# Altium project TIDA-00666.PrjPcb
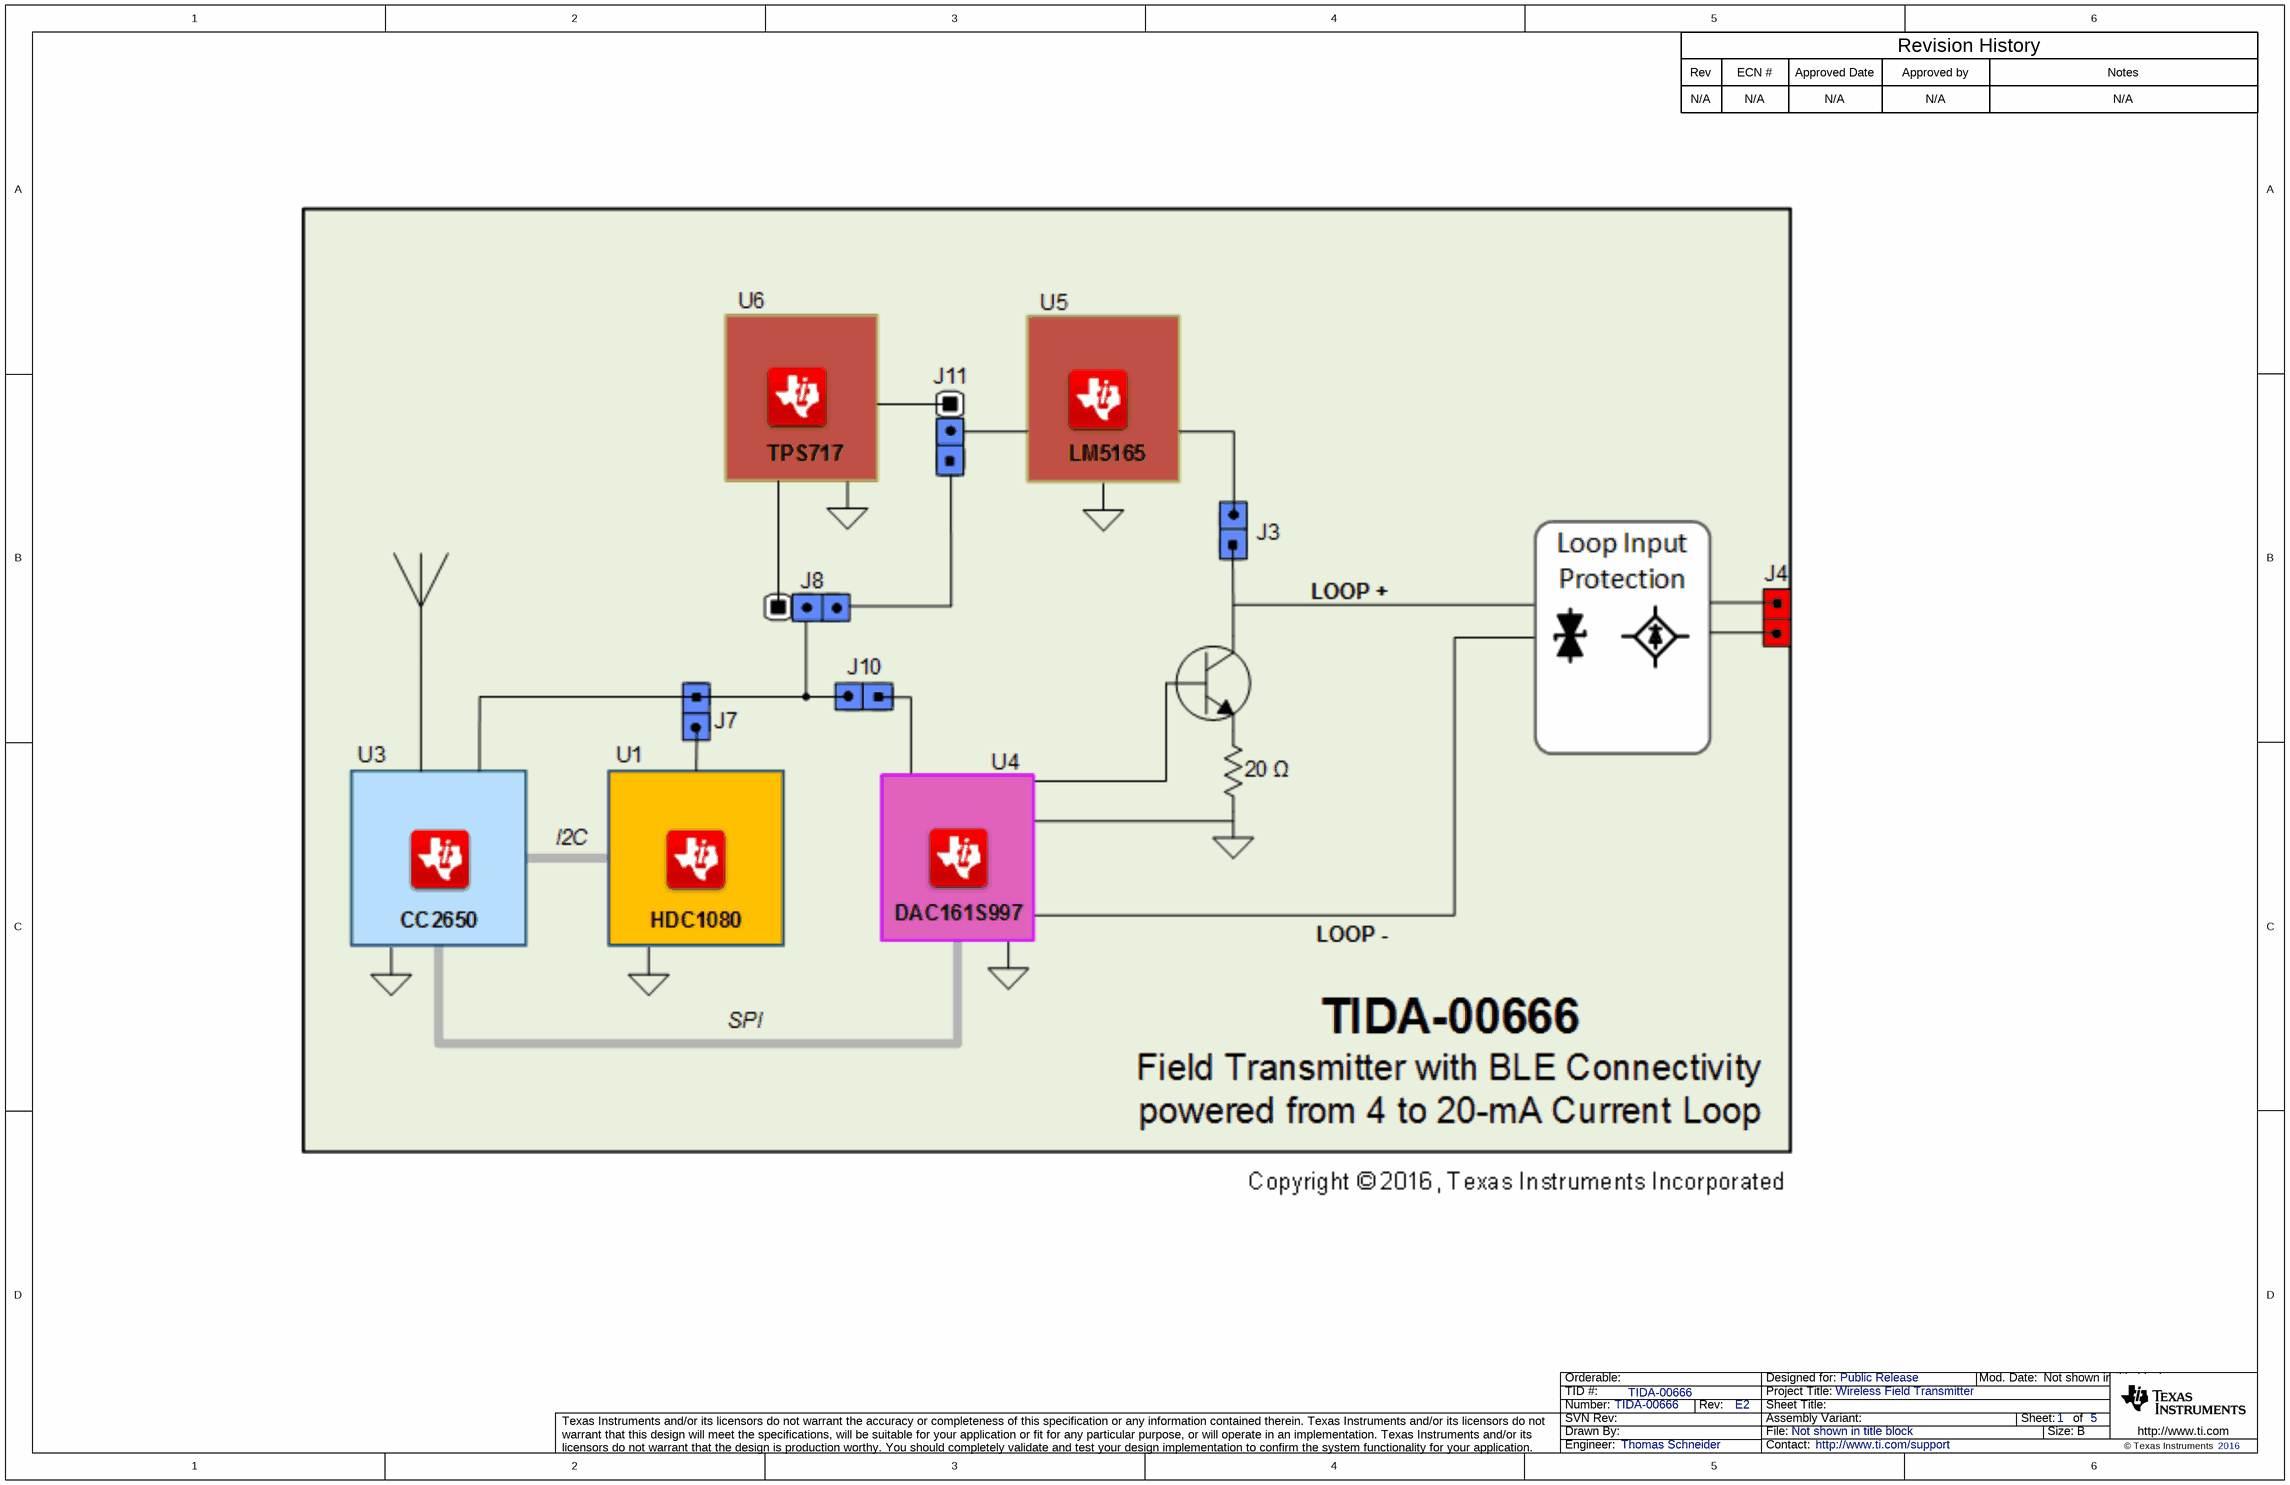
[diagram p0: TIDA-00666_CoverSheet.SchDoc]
CopyrightYear: 2016; PCB_Rev: E2; PRJ_Customer: Public Release; PRJ_Engineer: Thomas Schneider; PRJ_Number: TIDA-00666; PRJ_Title: Wireless Field Transmitter; SCH_Rev: E2; TechSupport: http://www.ti.com/support; TID: TIDA-00666
5 sheets, 113 parts. Net scope: global (net labels, ports and power ports of the same name join across sheets).
Board file: TIDA-00666_PCB.PcbDoc
Sheets:
  TIDA-00666_CoverSheet.SchDoc
  TIDA-00666_MCU.SchDoc
  TIDA-00666_Hardware.SchDoc
  TIDA-00666_DAC.SchDoc
  TIDA-00666_Power.SchDoc

## Sheet TIDA-00666_CoverSheet.SchDoc
size 431 x 279 mm; Date: Not shown in title block; ApprovedBy: Not shown in title block; CheckedBy: Not shown in title block; Author: Not shown in title block; CompanyName: Not shown in title block; Engineer: Not shown in title block; Organization: Not shown in title block; Address1: Not shown in title block; Address2: Not shown in title block; Address3: Not shown in title block; Address4: Not shown in title block; DocumentNumber: 1; Revision: Use project parameter SCH_Rev; SheetNumber: 1; SheetTotal: 5; PageSetup: Record=PageOptions¦CenterHorizontal=True¦CenterVertical=True¦PrintScale=1.00¦XCorrection=1.00¦YCorrection=1.00¦PrintKind=0¦BorderSize=5000000¦LeftOffset=0¦BottomOffset=0¦Orientation=2¦PaperLength=1000¦PaperWidth=1000¦Scale=100¦PaperSource=15¦PrintQuality=600¦MediaType=1¦DitherType=10¦PaperKind=Letter¦PrintScaleMode=1

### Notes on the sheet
- Rev
- N/A
- ECN #
- Approved Date
- Approved by
- Revision History
- Notes

## Sheet TIDA-00666_MCU.SchDoc
size 431 x 279 mm; Date: Not shown in title block; ApprovedBy: Not shown in title block; CheckedBy: Not shown in title block; Author: Not shown in title block; CompanyName: Not shown in title block; Engineer: Not shown in title block; Organization: Not shown in title block; Address1: Not shown in title block; Address2: Not shown in title block; Address3: Not shown in title block; Address4: Not shown in title block; DocumentNumber: 1; Revision: Use project parameter SCH_Rev; SheetNumber: 2; SheetTotal: 5; PageSetup: Record=PageOptions¦CenterHorizontal=True¦CenterVertical=True¦PrintScale=1.00¦XCorrection=1.00¦YCorrection=1.00¦PrintKind=0¦BorderSize=5000000¦LeftOffset=0¦BottomOffset=0¦Orientation=2¦PaperLength=1000¦PaperWidth=1000¦Scale=100¦PaperSource=15¦PrintQuality=600¦MediaType=1¦DitherType=10¦PaperKind=Letter¦PrintScaleMode=1
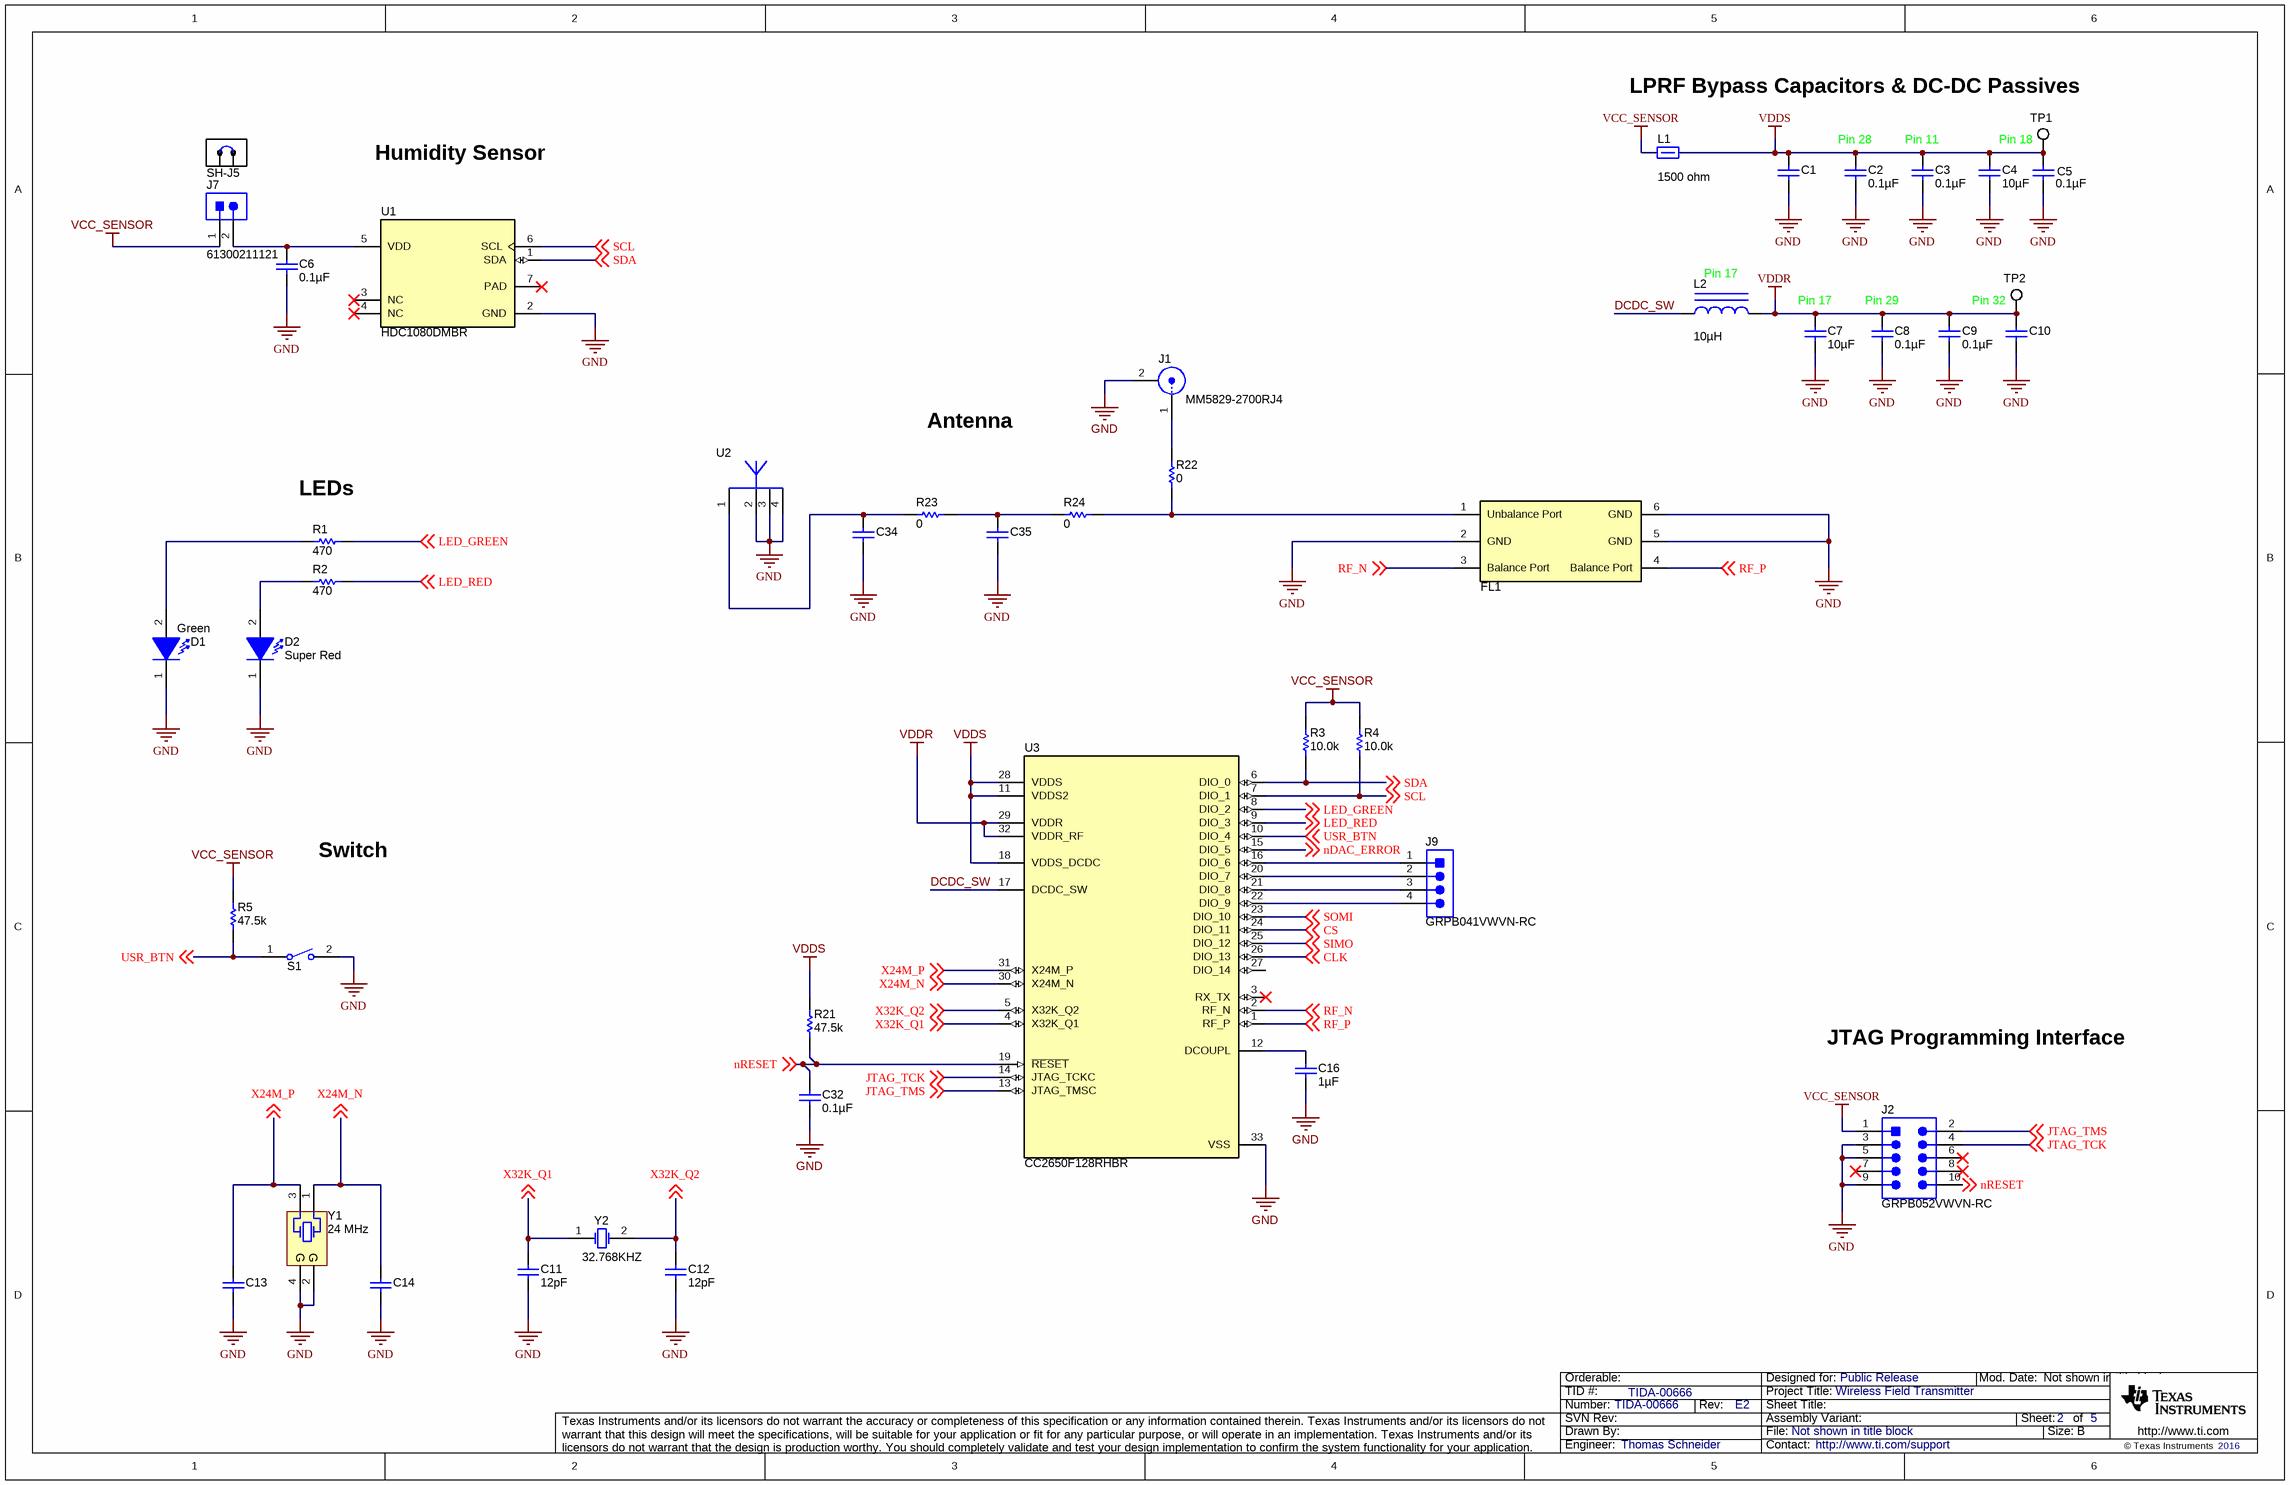
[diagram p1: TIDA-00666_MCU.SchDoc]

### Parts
C1  Used in BOM report  [0603]  (value not drawn)
C2  ValueDisplayed: 0.1µF  [0402]  (hidden comment: GRM155R70J104KA01D)
C3  ValueDisplayed: 0.1µF  [0402]  (hidden comment: GRM155R70J104KA01D)
C4  ValueDisplayed: 10µF  [0805_HV]  (hidden comment: GRM21BR70J106KE76L)
C5  ValueDisplayed: 0.1µF  [0402]  (hidden comment: GRM155R70J104KA01D)
C6  ValueDisplayed: 0.1µF  [0402]  (hidden comment: GRM155R70J104KA01D)
C7  ValueDisplayed: 10µF  [0805_HV]  (hidden comment: GRM21BR70J106KE76L)
C8  ValueDisplayed: 0.1µF  [0402]  (hidden comment: GRM155R70J104KA01D)
C9  ValueDisplayed: 0.1µF  [0402]  (hidden comment: GRM155R70J104KA01D)
C10  Used in BOM report  [0402]  (value not drawn)
C11  ValueDisplayed: 12pF  [0603]  (hidden comment: 06035A120JAT2A)
C12  ValueDisplayed: 12pF  [0603]  (hidden comment: 06035A120JAT2A)
C13  Used in BOM report  [0603]  (value not drawn)
C14  Used in BOM report  [0603]  (value not drawn)
C16  ValueDisplayed: 1µF  [0603]  (hidden comment: GRM188R70J105KA01D)
C32  ValueDisplayed: 0.1µF  [0402]  (hidden comment: GRM155R70J104KA01D)
C34  Used in BOM report  [0402]  (value not drawn)
C35  Used in BOM report  [0402]  (value not drawn)
D1  value Green  [WL-SMCW_GREEN]  (hidden comment: 150060VS75000)
D2  value Super Red  [WL-SMCW_RED]  (hidden comment: 150060SS75000)
FL1  LFB182G45BG5D920  [Murata_LFB182G45BG5D920]  (value not drawn)
J1  MM5829-2700RJ4  [MuRata_MM5829-2700]
J2  GRPB052VWVN-RC  [CONN_GRPB052VWVN-RC]
J7  61300211121  [WURTH_61300211121]
J9  GRPB041VWVN-RC  [Sullins_GRPB041VWVN-RC]
L1  value 1500 ohm  [0603]  (hidden comment: BLM18HE152SN1D)
L2  ValueDisplayed: 10µH  [0805_145]  (hidden comment: CKS2125100M-T)
R1  ValueDisplayed: 470  [0402]  (hidden comment: CRCW0402470RJNED)
R2  ValueDisplayed: 470  [0402]  (hidden comment: CRCW0402470RJNED)
R3  ValueDisplayed: 10.0k  [0402]  (hidden comment: CRCW040210K0FKED)
R4  ValueDisplayed: 10.0k  [0402]  (hidden comment: CRCW040210K0FKED)
R5  ValueDisplayed: 47.5k  [0402]  (hidden comment: CRCW040247K5FKED)
R21  ValueDisplayed: 47.5k  [0402]  (hidden comment: CRCW040247K5FKED)
R22  ValueDisplayed: 0  [0402]  (hidden comment: CRCW04020000Z0ED)
R23  ValueDisplayed: 0  [0402]  (hidden comment: CRCW04020000Z0ED)
R24  ValueDisplayed: 0  [0402]  (hidden comment: CRCW04020000Z0ED)
S1  434121025816  [SW_434121025816]  (value not drawn)
SH-J5  969102-0000-DA  [SNT-100-BK-G]  (value not drawn)
TP1  5015  [Testpoint_Keystone_Miniature]  (value not drawn)
TP2  5015  [Testpoint_Keystone_Miniature]  (value not drawn)
U1  HDC1080DMBR  [DMB0006A]
U2  2450AT18D0100E  [JohansonTech_2450AT18D0100E]  (value not drawn)
U3  CC2650F128RHBR  [RHB0032E]
Y1  Frequency: 24 MHz  [EPSON_TSX-3225]  (hidden comment: TSX-3225 24.0000MF20G-AC3)
Y2  Frequency: 32.768KHZ  [Epson_FC-12M]  (hidden comment: FC-12M 32.7680KA-A3)

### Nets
GND: C1.2 C2.2 C3.2 C4.2 C5.2 C6.2 C7.2 C8.2 C9.2 C10.2 C11.1 C12.2 C13.2 C14.2 C16.2 C32.2 C34.2 C35.2 D1.1(K) D2.1(K) FL1.2(GND) FL1.5(GND) FL1.6(GND) J1.2 J2.3 J2.5 J2.9 S1.2 U1.2(GND) U2.2(GND) U2.3(GND) U2.4(GND) U3.33(VSS) Y1.2(GND) Y1.4(GND)
VCC_SENSOR: J2.1 J7.1 L1.2 R3.2 R4.2 R5.2
VDDR: C7.1 C8.1 C9.1 C10.1 L2.2 TP2.1 U3.29(VDDR) U3.32(VDDR_RF)
VDDS: C1.1 C2.1 C3.1 C4.1 C5.1 L1.1 R21.2 TP1.1 U3.11(VDDS2) U3.18(VDDS_DCDC) U3.28(VDDS)
CLK: U3.26(DIO_13) ; off-sheet CLK
CS: U3.24(DIO_11) ; off-sheet CS
DCDC_SW: L2.1 U3.17(DCDC_SW)
JTAG_TCK: J2.4 U3.14(JTAG_TCKC) ; off-sheet JTAG_TCK
JTAG_TMS: J2.2 U3.13(JTAG_TMSC) ; off-sheet JTAG_TMS
LED_GREEN: R1.2 U3.8(DIO_2) ; off-sheet LED_GREEN
LED_RED: R2.1 U3.9(DIO_3) ; off-sheet LED_RED
nDAC_ERROR: U3.15(DIO_5) ; off-sheet nDAC_ERROR
nRESET: C32.1 J2.10 R21.1 U3.19(~{RESET}) ; off-sheet nRESET
RF_N: FL1.3(Balance_Port) U3.2(RF_N) ; off-sheet RF_N
RF_P: FL1.4(Balance_Port) U3.1(RF_P) ; off-sheet RF_P
SCL: R4.1 U1.6(SCL) U3.7(DIO_1) ; off-sheet SCL
SDA: R3.1 U1.1(SDA) U3.6(DIO_0) ; off-sheet SDA
SIMO: U3.25(DIO_12) ; off-sheet SIMO
SOMI: U3.23(DIO_10) ; off-sheet SOMI
USR_BTN: R5.1 S1.1 U3.10(DIO_4) ; off-sheet USR_BTN
X24M_N: C14.1 U3.30(X24M_N) Y1.1 ; off-sheet X24M_N
X24M_P: C13.1 U3.31(X24M_P) Y1.3 ; off-sheet X24M_P
X32K_Q1: C11.2 U3.4(X32K_Q1) Y2.1(OSC1) ; off-sheet X32K_Q1
X32K_Q2: C12.1 U3.5(X32K_Q2) Y2.2(OSC2) ; off-sheet X32K_Q2
NetC6_1: C6.1 J7.2 U1.5(VDD)
NetC16_1: C16.1 U3.12(DCOUPL)
NetC34_1: C34.1 R23.2 U2.1(Feeding_Point)
NetC35_1: C35.1 R23.1 R24.1
NetD1_2: D1.2(A) R1.1
NetD2_2: D2.2(A) R2.2
NetFL1_1: FL1.1(Unbalance_Port) R22.1 R24.2
NetJ1_1: J1.1 R22.2
NetJ9_1: J9.1 U3.16(DIO_6)
NetJ9_2: J9.2 U3.20(DIO_7)
NetJ9_3: J9.3 U3.21(DIO_8)
NetJ9_4: J9.4 U3.22(DIO_9)

Not connected (* = marked no-connect by the designer): J2 6* 7* 8*; U1 3(NC)* 4(NC)* 7(PAD)*; U3 3(RX_TX)* 27(DIO_14)

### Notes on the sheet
- LPRF Bypass Capacitors & DC-DC Passives
- Humidity Sensor
- (near C2) Pin 28
- (near C3) Pin 11
- (near TP1) Pin 18
- (near L2) Pin 17
- (near C7) Pin 17
- (near C8) Pin 29
- (near TP2) Pin 32
- Antenna
- (near R1) LEDs
- Switch
- JTAG Programming Interface

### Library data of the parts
C1 C10 C13 C14 C34 C35 = Capacitor: CAP, CERM, xxxF, xxV, [TempCo], xx%, [PackageReference]; Polarized: N; U/M: EA
C2 C3 C5 C6 C8 C9 C32 = GRM155R70J104KA01D: CAP, CERM, 0.1 µF, 6.3 V, +/- 10%, X7R, 0402; Manufacturer: MuRata; Polarized: N; CompType: Capacitor; Value: 0.1uF; U/M: EA; Cap_F: 0.0000001; Tolerance_%: 10; Value1: Unknown; VDC_V: 6.3; Value2: 6.3V; TaMin_C: -55; TaMax_C: 125; AEC Category: Q200
C4 C7 = GRM21BR70J106KE76L: CAP, CERM, 10 µF, 6.3 V, +/- 10%, X7R, 0805; Manufacturer: MuRata; Polarized: N; CompType: Capacitor; Value: 10uF; U/M: EA; Cap_F: 0.00001; Tolerance_%: 10; Value1: Unknown; VDC_V: 6.3; Value2: 6.3V; TaMin_C: -55; TaMax_C: 125; Cap_Case: 0805; AEC Category: Q200
C11 C12 = 06035A120JAT2A: CAP, CERM, 12 pF, 50 V, +/- 5%, C0G/NP0, 0603; Manufacturer: AVX; Polarized: N; CompType: Capacitor; Value: 12pF; U/M: EA; Cap_F: 0.000000000012; Tolerance_%: 5; ESR_ohm: 0.363; Value1: 0.363 ohm; VDC_V: 50; Value2: 50V; TaMin_C: -55; TaMax_C: 125
C16 = GRM188R70J105KA01D: CAP, CERM, 1 µF, 6.3 V, +/- 10%, X7R, 0603; Manufacturer: MuRata; Polarized: N; CompType: Capacitor; Value: 1uF; U/M: EA; Cap_F: 0.000001; Tolerance_%: 10; Value1: Unknown; VDC_V: 6.3; Value2: 6.3V; TaMin_C: -55; TaMax_C: 125; AEC Category: Q200
D1 = 150060VS75000: LED, Green, SMD; Manufacturer: Wurth Elektronik; Type: AlInGaP; Vf_V: 2; Value2: 2V; Io_A: 0.02; Value1: W; U/M: EA
D2 = 150060SS75000: LED, Super Red, SMD; Manufacturer: Wurth Elektronik; Type: AlInGaP; Vf_V: 1.9; Value2: 1.9V; Io_A: 0.02; Value1: W; U/M: EA
FL1 = LFB182G45BG5D920: Filter, BandPass, 2.45GHz, SMD; Manufacturer: MuRata; SymbolCreator: Altium
J1 = MM5829-2700RJ4: Connector, RF, 50 Ohm, SMT; Manufacturer: MuRata; SymbolCreator: a0799628; Gender: Male; Shrouded: Y; ContactFinish: Gold
J2 = GRPB052VWVN-RC: Header, 50mil, 5x2, Gold, TH; Manufacturer: Sullins Connector Solutions; SymbolCreator: a0412235; U/M: EA
J7 = 61300211121: Header, 2.54 mm, 2x1, Gold, TH; Manufacturer: Wurth Elektronik; SymbolCreator: a0412235
J9 = GRPB041VWVN-RC: Header, 50mil, 4x1, Gold, TH; Manufacturer: Sullins Connector Solutions; SymbolCreator: a0412235
L1 = BLM18HE152SN1D: Ferrite Bead, 1500 ohm @ 100 MHz, 0.5 A, 0603; Manufacturer: MuRata; Imax_A: 0.5; Value1: 0.5 ohm; Value2: 0.5A; ZTyp@100MHz_Ohm: 1500
L2 = CKS2125100M-T: Inductor, Multilayer, Ferrite, 10 µH, 0.11 A, 0.52 ohm, SMD; Manufacturer: Taiyo Yuden; Value: 10uH; Ind_H: 10.0E-6; Imax_A: 0.11; DCR_ohm: 0.52; Value2: 0.11A; AEC Category: Q200
R1 R2 = CRCW0402470RJNED: RES, 470, 5%, 0.063 W, 0402; Manufacturer: Vishay-Dale; CompType: Resistor; Value: 470; Value_Code: 470R; Tolerance_%: 5; Power_W: 0.063; Value2: 0.063W; VDC_V: 50; TempCo: 200 ppm/C; EIA_Code: E24; U/M: EA; AEC Category: Q200
R3 R4 = CRCW040210K0FKED: RES, 10.0 k, 1%, 0.063 W, 0402; Manufacturer: Vishay-Dale; CompType: Resistor; Value: 10.0k; Res_ohm: 10000; Value_Code: 10k0; Tolerance_%: 1; Power_W: 0.063; Value2: 0.063W; VDC_V: 50; TempCo: 100 ppm/C; EIA_Code: E96; U/M: EA
R5 = CRCW040247K5FKED: RES, 47.5 k, 1%, 0.063 W, 0402; Manufacturer: Vishay-Dale; CompType: Resistor; Res_ohm: 47500; Value: 47.5k; Value_Code: 47k5; Tolerance_%: 1; Power_W: 0.063; Value2: 0.063W; VDC_V: 50; TempCo: 100 ppm/C; EIA_Code: E96; U/M: EA
R21 = CRCW040247K5FKED: RES, 47.5 k, 1%, 0.063 W, 0402; Manufacturer: Vishay-Dale; CompType: Resistor; Value: 47.5k; Res_ohm: 47500; Value_Code: 47k5; Tolerance_%: 1; Power_W: 0.063; Value2: 0.063W; VDC_V: 50; TempCo: 100 ppm/C; EIA_Code: E96; U/M: EA; AEC Category: Q200
R22 R24 = CRCW04020000Z0ED: RES, 0, 5%, 0.063 W, 0402; Manufacturer: Vishay-Dale; CompType: Resistor; Value: 0; Value_Code: 0000; Tolerance_%: 5; Power_W: 0.063; Value2: 0.063W; VDC_V: 50; TempCo: 200 ppm/C; SizeArea_mm2: 0.5; SizeX_mm: 1; SizeZ_mm: 0.6; EIA_Code: E24; U/M: EA; AEC Category: Q200
R23 = CRCW04020000Z0ED: RES, 0, 5%, 0.063 W, 0402; Manufacturer: Vishay-Dale; CompType: Resistor; Value: 0; Value_Code: 0000; Tolerance_%: 5; Power_W: 0.063; Value2: 0.063W; VDC_V: 50; TempCo: 200 ppm/C; EIA_Code: E24; U/M: EA; AEC Category: Q200
S1 = 434121025816: Switch, Tactile, SPST, 12 V, SMD; Manufacturer: Wurth Elektronik; SymbolCreator: a0799628; VDC_V: 12; SwitchFunction: Off-On; PositionCount: 1; CurrentRating_mA: 50
SH-J5 = 969102-0000-DA: Shunt, 100mil, Gold plated, Black; Manufacturer: 3M; Alternate Manufacturer: Samtec; Value: 1x2; Note: You can "mate" this to a header by matching the designator.  i.e. use SH-J3 for header J3
TP1 TP2 = 5015: Test Point, Miniature, SMT; Manufacturer: Keystone; CompType: Test Point Loop; U/M: EA
U1 = HDC1080DMBR: Low Power, High Accuracy Digital Humidity Sensor with Temperature Sensor, DMB0006A; Alternate PartNumber: HDC1080DMBT; Manufacturer: Texas Instruments; SymbolCreator: a0411947; CompType: IC; U/M: EA
U2 = 2450AT18D0100E: 2.45 GHz Antenna, EIA 1210, Detuning resilient, Edge Mount, SMD; Manufacturer: Johanson Technology; SymbolCreator: Altium
U3 = CC2650F128RHBR: Ultra low-power ARM Cortex M3 2.4 GHz Radio MCU, Multi-Protocol, RSHB032E; Alternate PartNumber: CC2650F128RHBT; Manufacturer: Texas Instruments; SymbolCreator: a0412235; CompType: IC; U/M: EA
Y1 = TSX-3225 24.0000MF20G-AC3: Crystal, 24 MHz, 9 pF, SMD; Manufacturer: Epson; SymbolCreator: a0412235; U/M: EA; TaMin_C: -40; TaMax_C: 85; Frequency Stability: ±20ppm
Y2 = FC-12M 32.7680KA-A3: Crystal, 32.768kHz, 12.5pF, SMD; Manufacturer: Epson; SymbolCreator: a0412235; U/M: EA; TaMin_C: -40; TaMax_C: 85; Frequency Stability: ±20ppm

## Sheet TIDA-00666_Hardware.SchDoc
size 431 x 279 mm; Date: Not shown in title block; ApprovedBy: Not shown in title block; CheckedBy: Not shown in title block; Author: Not shown in title block; CompanyName: Not shown in title block; Engineer: Not shown in title block; Organization: Not shown in title block; Address1: Not shown in title block; Address2: Not shown in title block; Address3: Not shown in title block; Address4: Not shown in title block; DocumentNumber: 1; Revision: Use project parameter SCH_Rev; SheetNumber: 3; SheetTotal: 5; PageSetup: Record=PageOptions¦CenterHorizontal=True¦CenterVertical=True¦PrintScale=1.00¦XCorrection=1.00¦YCorrection=1.00¦PrintKind=0¦BorderSize=5000000¦LeftOffset=0¦BottomOffset=0¦Orientation=2¦PaperLength=1000¦PaperWidth=1000¦Scale=100¦PaperSource=15¦PrintQuality=600¦MediaType=1¦DitherType=10¦PaperKind=Letter¦PrintScaleMode=1
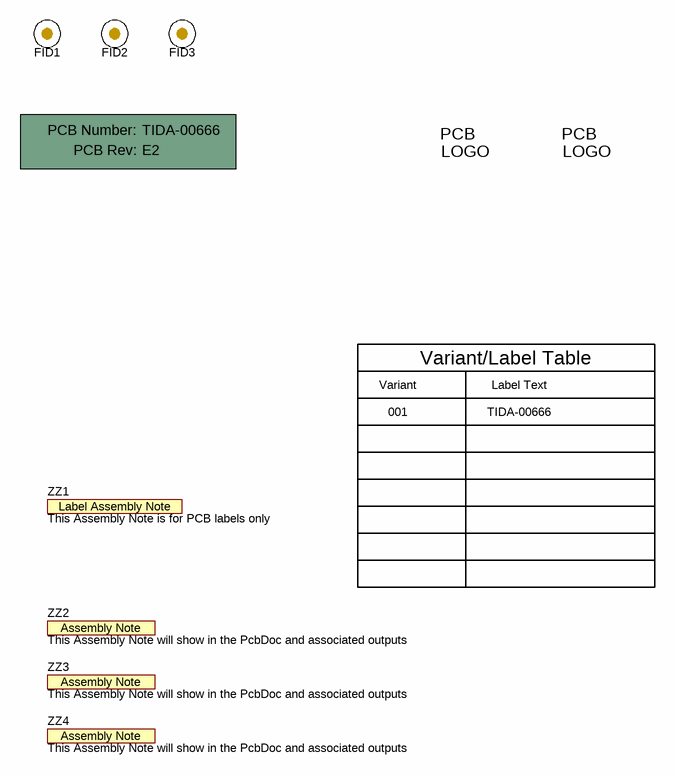
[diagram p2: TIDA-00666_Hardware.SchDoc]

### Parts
!PCB1  Printed Circuit Board  (value not drawn)  (mechanical)
FID1  Fiducial  [Fiducial10-20]  (value not drawn)
FID2  Fiducial  [Fiducial10-20]  (value not drawn)
FID3  Fiducial  [Fiducial10-20]  (value not drawn)
Logo2  Pb-Free Symbol  [Pb-Free_Overlay_Small]  (value not drawn)  (no BOM)
Logo3  FCC disclaimer  [FCC_disclaimer_stacked]  (value not drawn)  (no BOM)
ZZ1  This Assembly Note is for PCB labels only  [AssemblyNoteLabel]  (no BOM)
ZZ2  This Assembly Note will show in the PcbDoc and associated outputs  [AssemblyNote]  (no BOM)
ZZ3  This Assembly Note will show in the PcbDoc and associated outputs  [AssemblyNote]  (no BOM)
ZZ4  This Assembly Note will show in the PcbDoc and associated outputs  [AssemblyNote]  (no BOM)

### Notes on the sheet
- Variant
- Variant/Label Table
- Label Text
- 001
- TIDA-00666

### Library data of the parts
!PCB1 = PCB: Manufacturer: Any; PartNumber: TIDA-00666; SymbolCreator: a0412235
FID1-FID3 = Fiducial: Fiducial mark.  There is nothing to buy or mount.; SymbolCreator: codlsc
Logo2 = Pb-Free: SymbolCreator: a0412235
Logo3 = FCC_disclaimer: SymbolCreator: a0412235
ZZ1 = AssemblyNoteLabel: SymbolCreator: a0412235
ZZ2-ZZ4 = AssemblyNote: SymbolCreator: codlsc

## Sheet TIDA-00666_DAC.SchDoc
size 431 x 279 mm; Date: Not shown in title block; ApprovedBy: Not shown in title block; CheckedBy: Not shown in title block; Author: Not shown in title block; CompanyName: Not shown in title block; Engineer: Not shown in title block; Organization: Not shown in title block; Address1: Not shown in title block; Address2: Not shown in title block; Address3: Not shown in title block; Address4: Not shown in title block; DocumentNumber: 1; Revision: Use project parameter SCH_Rev; SheetNumber: 4; SheetTotal: 5; PageSetup: Record=PageOptions¦CenterHorizontal=True¦CenterVertical=True¦PrintScale=1.00¦XCorrection=1.00¦YCorrection=1.00¦PrintKind=0¦BorderSize=5000000¦LeftOffset=0¦BottomOffset=0¦Orientation=2¦PaperLength=1000¦PaperWidth=1000¦Scale=100¦PaperSource=15¦PrintQuality=600¦MediaType=1¦DitherType=10¦PaperKind=Letter¦PrintScaleMode=1
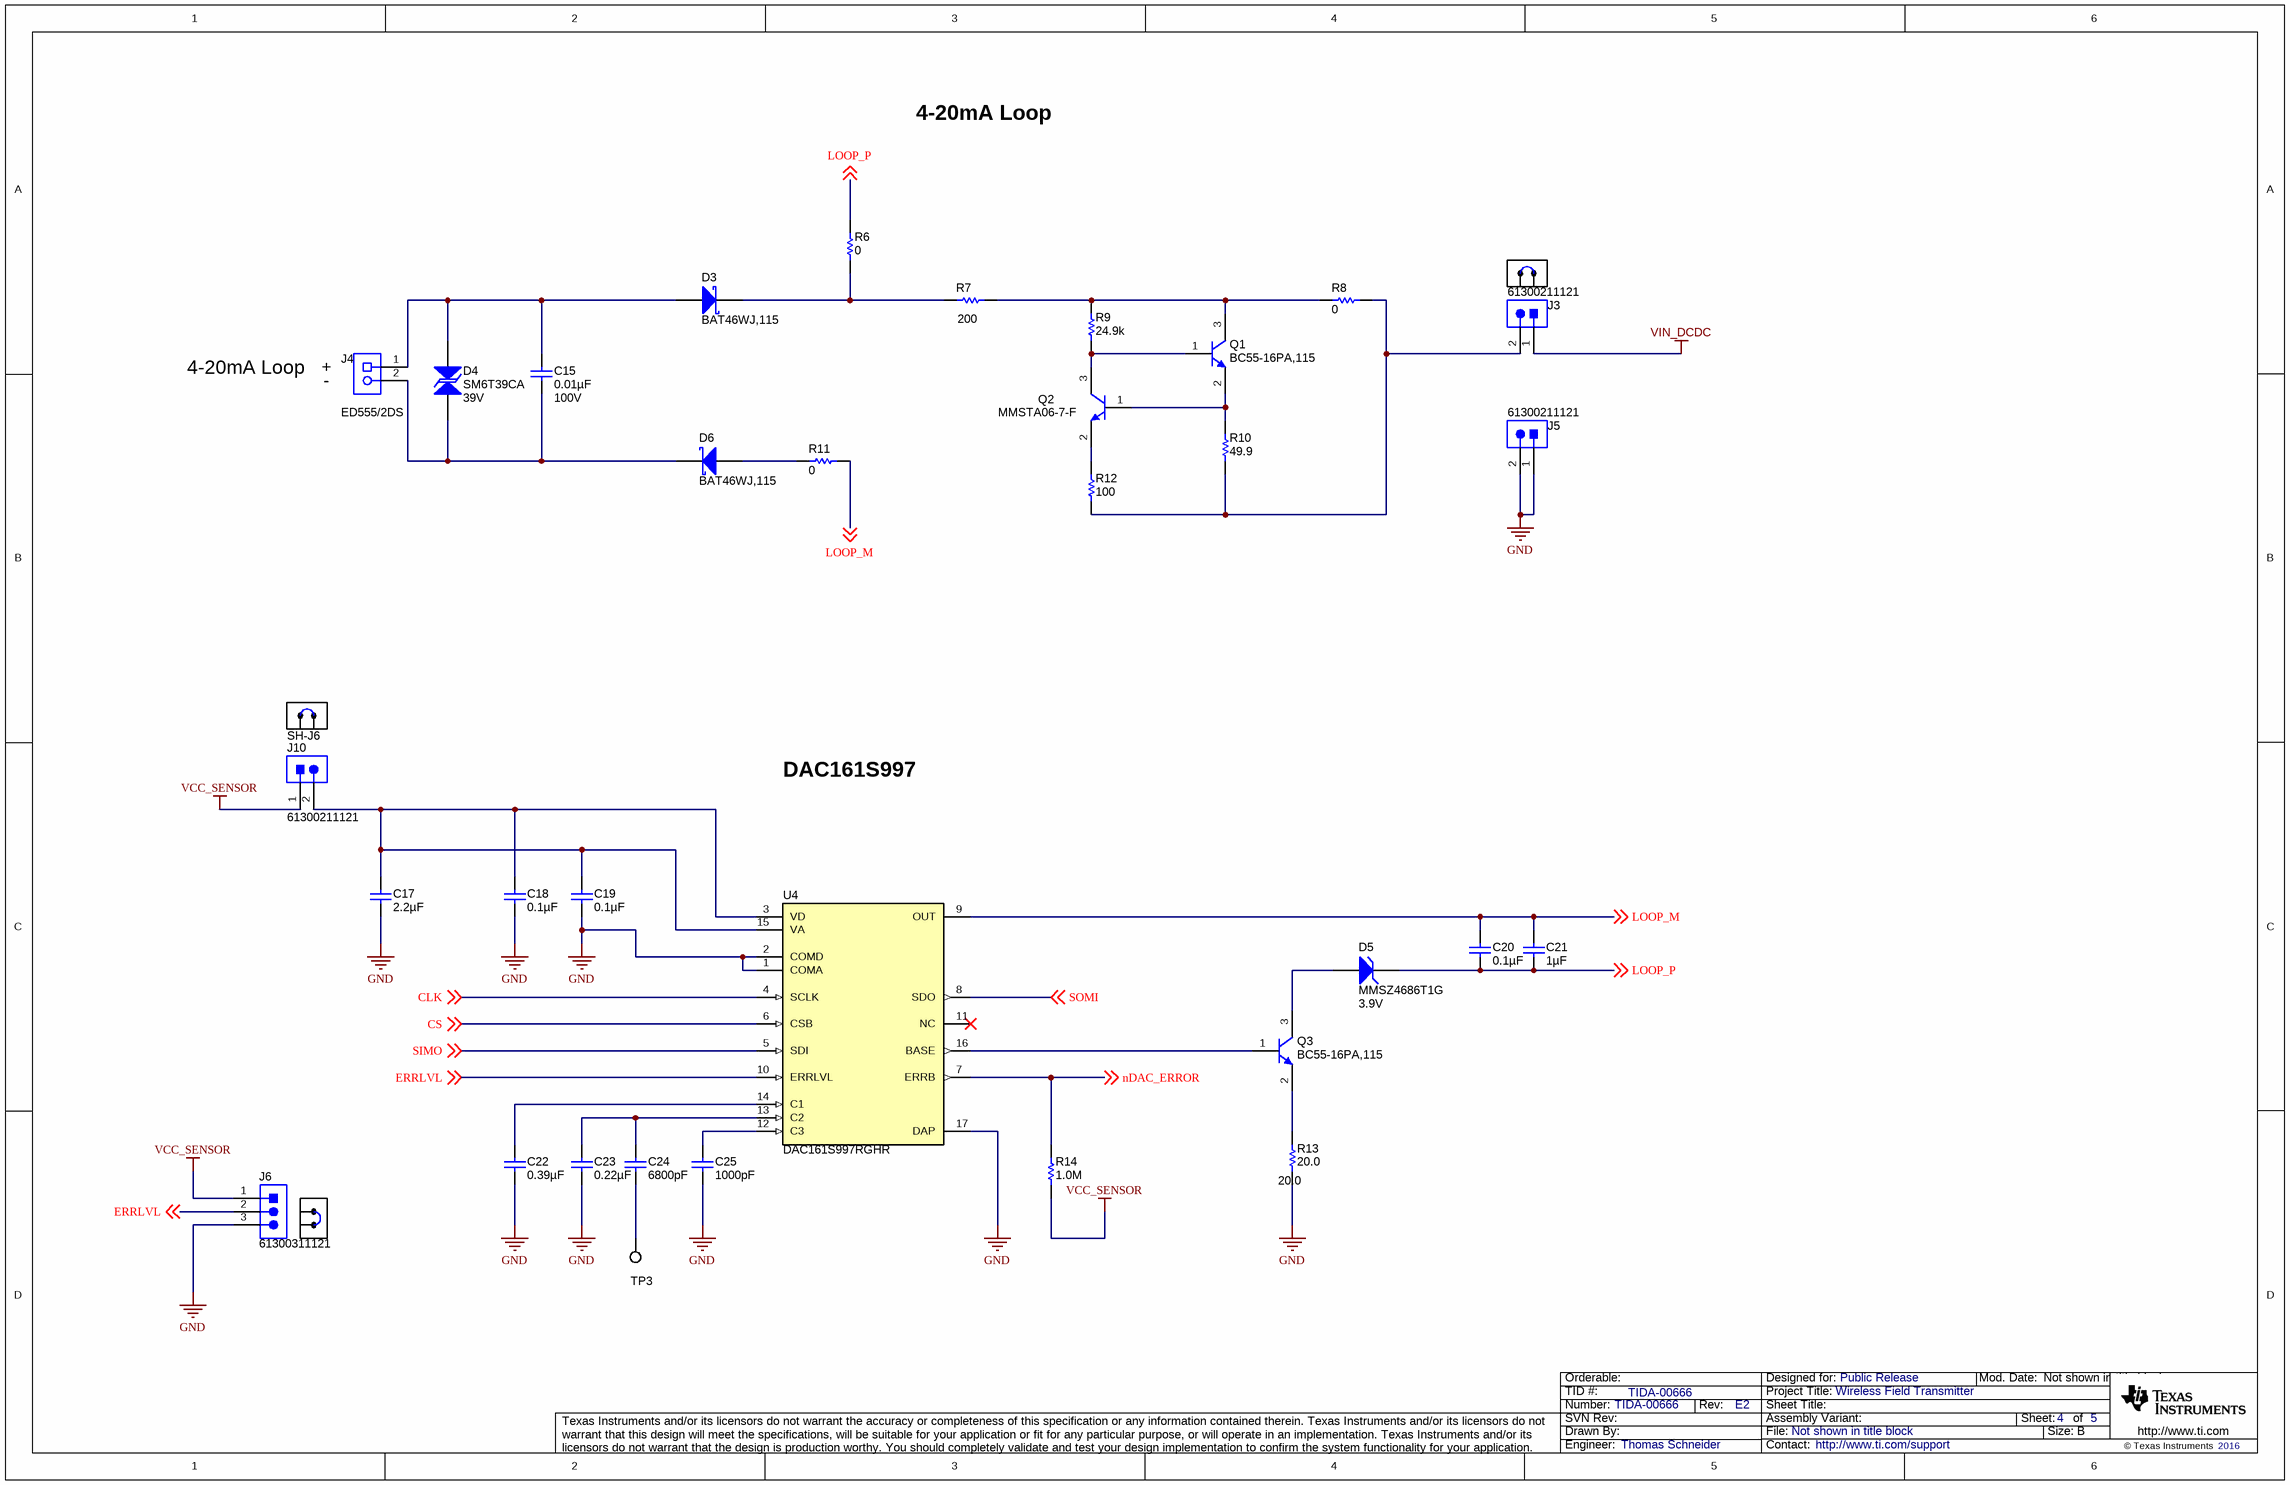
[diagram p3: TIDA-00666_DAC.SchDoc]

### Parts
C15  ValueDisplayed: 0.01µF  Value2: 100V  [0603]  (hidden comment: C1608X7R2A103K)
C17  ValueDisplayed: 2.2µF  [0402]  (hidden comment: C1005X5R1C225K050BC)
C18  ValueDisplayed: 0.1µF  [0402]  (hidden comment: C1005X5R0J104K)
C19  ValueDisplayed: 0.1µF  [0402]  (hidden comment: C1005X5R0J104K)
C20  ValueDisplayed: 0.1µF  [1206]  (hidden comment: 12061C104JAT2A)
C21  ValueDisplayed: 1µF  [1206]  (hidden comment: GRM31CR72A105KA01L)
C22  ValueDisplayed: 0.39µF  [0402]  (hidden comment: GRM155R61A394KE15D)
C23  ValueDisplayed: 0.22µF  [0402]  (hidden comment: GRM155R60J224KE01D)
C24  ValueDisplayed: 6800pF  [0402]  (hidden comment: GRM155R71E682KA01D)
C25  ValueDisplayed: 1000pF  [0402]  (hidden comment: GRM155R60J102KA01D)
D3  BAT46WJ,115  [SOD-323F]
D4  SM6T39CA  value 39V  [SMB-Bi]
D5  MMSZ4686T1G  value 3.9V  [SOD-123]
D6  BAT46WJ,115  [SOD-323F]
J3  61300211121  [WURTH_61300211121]
J4  ED555/2DS  [TERM_BLK_ED555-2DS]
J5  61300211121  [WURTH_61300211121]
J6  61300311121  [WURTH_61300311121]
J10  61300211121  [WURTH_61300211121]
Q1  BC55-16PA,115  [SOT1061]
Q2  MMSTA06-7-F  [SOT-323]
Q3  BC55-16PA,115  [SOT1061]
R6  ValueDisplayed: 0  [0603]  (hidden comment: CRCW06030000Z0EA)
R7  ValueDisplayed: 200  [1206]  (hidden comment: CRCW1206200RFKEA)
R8  ValueDisplayed: 0  [0603]  (hidden comment: CRCW06030000Z0EA)
R9  ValueDisplayed: 24.9k  [0603]  (hidden comment: CRCW060324K9FKEA)
R10  ValueDisplayed: 49.9  [1206]  (hidden comment: CRCW120649R9FKEA)
R11  ValueDisplayed: 0  [0603]  (hidden comment: CRCW06030000Z0EA)
R12  ValueDisplayed: 100  [0603]  (hidden comment: CRCW0603100RFKEA)
R13  value 20.0  [0603]  (hidden comment: CRCW060320R0FKEA)
R14  ValueDisplayed: 1.0M  [0402]  (hidden comment: CRCW04021M00JNED)
SH-J1  969102-0000-DA  [SNT-100-BK-G]  (value not drawn)
SH-J2  969102-0000-DA  [SNT-100-BK-G]  (value not drawn)
SH-J6  969102-0000-DA  [SNT-100-BK-G]  (value not drawn)
TP3  5015  [Testpoint_Keystone_Miniature]  (value not drawn)
U4  DAC161S997RGHR  [RGH0016A]

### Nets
GND: C17.2 C18.2 C19.2 C22.2 C23.2 C25.2 J5.1 J5.2 J6.3 R13.1 U4.1(COMA) U4.2(COMD) U4.17(DAP)
VCC_SENSOR: J6.1 J10.1 R14.1
VIN_DCDC: J3.1
CLK: U4.4(SCLK) ; off-sheet CLK
CS: U4.6(CSB) ; off-sheet CS
ERRLVL: J6.2 U4.10(ERRLVL) ; off-sheet ERRLVL
LOOP_M: C20.2 C21.2 R11.1 U4.9(OUT) ; off-sheet LOOP_M
LOOP_P: C20.1 C21.1 D5.1(K) R6.2 ; off-sheet LOOP_P
nDAC_ERROR: R14.2 U4.7(ERRB) ; off-sheet nDAC_ERROR
SIMO: U4.5(SDI) ; off-sheet SIMO
SOMI: U4.8(SDO) ; off-sheet SOMI
NetC15_1: C15.1 D3.2(A) D4.1 J4.1
NetC15_2: C15.2 D4.2 D6.1(K) J4.2
NetC17_1: C17.1 C18.1 C19.1 J10.2 U4.3(VD) U4.15(VA)
NetC22_1: C22.1 U4.14(C1)
NetC23_1: C23.1 C24.1 U4.13(C2)
NetC24_2: C24.2 TP3.1
NetC25_1: C25.1 U4.12(C3)
NetD3_1: D3.1(K) R6.1 R7.1
NetD5_2: D5.2(A) Q3.3(C)
NetD6_2: D6.2(A) R11.2
NetJ3_2: J3.2 R8.2 R10.1 R12.1
NetQ1_1: Q1.1(B) Q2.3(C) R9.1
NetQ1_2: Q1.2(E) Q2.1(B) R10.2
NetQ1_3: Q1.3(C) R7.2 R8.1 R9.2
NetQ2_2: Q2.2(E) R12.2
NetQ3_1: Q3.1(B) U4.16(BASE)
NetQ3_2: Q3.2(E) R13.2

Not connected (* = marked no-connect by the designer): U4 11(NC)*

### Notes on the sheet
- 4-20mA Loop
- (near J4) +
- (near J4) -
- DAC161S997

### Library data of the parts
C15 = C1608X7R2A103K: CAP, CERM, 0.01 µF, 100 V, +/- 10%, X7R, 0603; Manufacturer: TDK; Polarized: N; CompType: Capacitor; Value: 0.01uF; U/M: EA; Cap_F: 0.00000001; Tolerance_%: 10; ESR_ohm: 0.0661; Value1: 0.0661 ohm; VDC_V: 100; TaMin_C: -55; TaMax_C: 125; AEC Category: Q200
C17 = C1005X5R1C225K050BC: CAP, CERM, 2.2 µF, 16 V, +/- 10%, X5R, 0402; Manufacturer: TDK; Polarized: N; CompType: Capacitor; Value: 2.2uF; U/M: EA; Cap_F: 0.0000022; Tolerance_%: 10; Value1: Unknown; VDC_V: 16; Value2: 16V; TaMin_C: -55; TaMax_C: 85; AEC Category: Q200
C18 C19 = C1005X5R0J104K: CAP, CERM, 0.1 µF, 6.3 V, +/- 10%, X5R, 0402; Manufacturer: TDK; Polarized: N; CompType: Capacitor; Value: 0.1uF; U/M: EA; Cap_F: 0.0000001; Tolerance_%: 10; ESR_ohm: 0.0186; Value1: 0.0186 ohm; VDC_V: 6.3; Value2: 6.3V; TaMin_C: -55; TaMax_C: 85; AEC Category: Q200
C20 = 12061C104JAT2A: CAP, CERM, 0.1 µF, 100 V, +/- 5%, X7R, 1206; Manufacturer: AVX; Polarized: N; CompType: Capacitor; Value: 0.1uF; U/M: EA; Cap_F: 0.0000001; Tolerance_%: 5; ESR_ohm: 0.037; Value1: 0.037 ohm; VDC_V: 100; Value2: 100V; TaMin_C: -55; TaMax_C: 125; AEC Category: Q200
C21 = GRM31CR72A105KA01L: CAP, CERM, 1 µF, 100 V, +/- 10%, X7R, 1206; Manufacturer: MuRata; Polarized: N; CompType: Capacitor; Value: 1uF; U/M: EA; Cap_F: 0.000001; Tolerance_%: 10; Value1: Unknown; VDC_V: 100; Value2: 100V; TaMin_C: -55; TaMax_C: 125; Cap_Case: 2220; AEC Category: Q200
C22 = GRM155R61A394KE15D: CAP, CERM, 0.39 µF, 10 V, +/- 10%, X5R, 0402; Manufacturer: MuRata; Polarized: N; CompType: Capacitor; Value: 0.39uF; U/M: EA; Cap_F: 0.00000039; Tolerance_%: 10; Value1: Unknown; Value2: 10V; TaMin_C: -55; TaMax_C: 85; AEC Category: Q200
C23 = GRM155R60J224KE01D: CAP, CERM, 0.22 µF, 6.3 V, +/- 10%, X5R, 0402; Manufacturer: MuRata; Polarized: N; CompType: Capacitor; Value: 0.22uF; U/M: EA; Cap_F: 0.00000022; Tolerance_%: 10; Value1: Unknown; VDC_V: 6.3; Value2: 6.3V; TaMin_C: -55; TaMax_C: 85; AEC Category: Q200
C24 = GRM155R71E682KA01D: CAP, CERM, 6800 pF, 25 V, +/- 10%, X7R, 0402; Manufacturer: MuRata; Polarized: N; CompType: Capacitor; Value: 6800pF; U/M: EA; Cap_F: 0.0000000068; Tolerance_%: 10; Value1: Unknown; VDC_V: 25; Value2: 25V; TaMin_C: -55; TaMax_C: 125; AEC Category: Q200
C25 = GRM155R60J102KA01D: CAP, CERM, 1000 pF, 6.3 V, +/- 10%, X5R, 0402; Manufacturer: MuRata; Polarized: N; CompType: Capacitor; Value: 1000pF; U/M: EA; Cap_F: 0.000000001; Tolerance_%: 10; Value1: Unknown; VDC_V: 6.3; Value2: 6.3V; TaMin_C: -55; TaMax_C: 85; AEC Category: Q200
D3 D6 = BAT46WJ,115: Diode, Schottky, 100 V, 0.25 A, SOD-323F; Manufacturer: NXP Semiconductor; U/M: EA; Vf_V: 0.85; Value: 100V; Value1: 0.25A; Value2: 0.85V; Io_A: 0.25; Vr_V: 100; TJmax_C: 150; AEC Category: Q101
D4 = SM6T39CA: Diode, TVS, Bi, 39 V, 600 W, SMB; Manufacturer: STMicroelectronics; U/M: EA; Power_W: 600; Value1: 600W; RJA_CperW: 100; Vr_V: 39; AEC Category: Q101
D5 = MMSZ4686T1G: Diode, Zener, 3.9 V, 500 mW, SOD-123; Manufacturer: ON Semiconductor; U/M: EA; Power_W: 0.5; Vz_V: 3.9; Value1: 0.5W; RJA_CperW: 340; SymbolCreator: a0412235; AEC Category: Q101
J3 J5 J10 = 61300211121: as J7 on sheet TIDA-00666_MCU
J4 = ED555/2DS: Terminal Block, 3.5mm Pitch, 2x1, TH; Manufacturer: On-Shore Technology; SymbolCreator: a0412235; Pitch_mm: 3.5; Gender: Female; Shrouded: N; Row_Count: 1; ContactFinish: Brass; Current_A: 6; Voltage_V: 150; Cert_CULUS: Y
J6 = 61300311121: Header, 2.54 mm, 3x1, Gold, TH; Manufacturer: Wurth Elektronik; SymbolCreator: a0799628
Q1 = BC55-16PA,115, NXP Semiconductor: Transistor, NPN, 60 V, 1 A, AEC-Q101, SOT1061; CompType: BJT; PNP: 0; NPN: 1; Vceo_V: 60; Vcesat1_V: 0.5; Value: 60 V; Value1: 1 A; HfeMax: 250; TaMin_C: -55; TaMax_C: 150; U/M: EA; AEC Category: Q101; AEC Qualified: Y
Q2 = MMSTA06-7-F, Diodes Inc.: Transistor, NPN, 80 V, 0.5 A, SOT-323; CompType: BJT; PNP: 0; NPN: 1; Vceo_V: 80; Vcesat1_V: 0.25; Value: 80 V; IcRated_A: 0.5; Value1: 0.5 A; TaMin_C: -55; TaMax_C: 150; U/M: EA; AEC Category: Q101
Q3 = BC55-16PA,115, NXP Semiconductor: Transistor, NPN, 60 V, 1 A, AEC-Q101, SOT1061; PNP: 0; NPN: 1; Vceo_V: 60; Vcesat1_V: 0.5; Value: 60 V; Value1: 1 A; HfeMax: 250; TaMin_C: -55; TaMax_C: 150; CompType: BJT; U/M: EA; AEC Category: Q101; AEC Qualified: Y
R6 R8 R11 = CRCW06030000Z0EA: RES, 0, 5%, 0.1 W, 0603; Manufacturer: Vishay-Dale; CompType: Resistor; Value: 0; Value_Code: 0000; Tolerance_%: 5; Power_W: 0.1; Value2: 0.1W; VDC_V: 75; TempCo: 200 ppm/C; EIA_Code: E24; U/M: EA; AEC Category: Q200
R7 = CRCW1206200RFKEA: RES, 200, 1%, 0.25 W, 1206; Manufacturer: Vishay-Dale; CompType: Resistor; Value: 200; Value_Code: 200R; Tolerance_%: 1; Power_W: 0.25; Value2: 0.25W; TempCo: 100 ppm/C; EIA_Code: E96; U/M: EA; AEC Category: Q200
R9 = CRCW060324K9FKEA: RES, 24.9 k, 1%, 0.1 W, 0603; Manufacturer: Vishay-Dale; CompType: Resistor; Value: 24.9k; Res_ohm: 24900; Value_Code: 24k9; Tolerance_%: 1; Power_W: 0.1; Value2: 0.1W; VDC_V: 75; TempCo: 100 ppm/C; EIA_Code: E96; U/M: EA; AEC Category: Q200
R10 = CRCW120649R9FKEA: RES, 49.9, 1%, 0.25 W, 1206; Manufacturer: Vishay-Dale; CompType: Resistor; Value: 49.9; Value_Code: 49R9; Tolerance_%: 1; Power_W: 0.25; Value2: 0.25W; VDC_V: 200; TempCo: 100 ppm/C; EIA_Code: E96; U/M: EA; AEC Category: Q200
R12 = CRCW0603100RFKEA: RES, 100, 1%, 0.1 W, 0603; Manufacturer: Vishay-Dale; CompType: Resistor; Value: 100; Value_Code: 100R; Tolerance_%: 1; Power_W: 0.1; Value2: 0.1W; VDC_V: 75; TempCo: 100 ppm/C; EIA_Code: E96; U/M: EA; AEC Category: Q200
R13 = CRCW060320R0FKEA: RES, 20.0, 1%, 0.1 W, 0603; Manufacturer: Vishay-Dale; CompType: Resistor; Res_ohm: 20; Value_Code: 20R0; Tolerance_%: 1; Power_W: 0.1; Value2: 0.1W; VDC_V: 75; TempCo: 100 ppm/C; EIA_Code: E96; U/M: EA; AEC Category: Q200
R14 = CRCW04021M00JNED: RES, 1.0 M, 5%, 0.063 W, 0402; Manufacturer: Vishay-Dale; CompType: Resistor; Value: 1.0Meg; Res_ohm: 1000000; Value_Code: 1M00; Tolerance_%: 5; Power_W: 0.063; Value2: 0.063W; VDC_V: 50; TempCo: 200 ppm/C; EIA_Code: E24; U/M: EA; AEC Category: Q200
SH-J1 SH-J2 SH-J6 = 969102-0000-DA: as SH-J5 on sheet TIDA-00666_MCU
TP3 = 5015: as TP1 on sheet TIDA-00666_MCU
U4 = DAC161S997RGHR: 16-bit SPI Programmable DAC for 4-20mA Loops, RGH0016A; Alternate Manufacturer: Texas Instruments; Alternate PartNumber: DAC161S997RGHT; SymbolCreator: x0208325; CompType: IC; U/M: EA

## Sheet TIDA-00666_Power.SchDoc
size 431 x 279 mm; Date: Not shown in title block; ApprovedBy: Not shown in title block; CheckedBy: Not shown in title block; Author: Not shown in title block; CompanyName: Not shown in title block; Engineer: Not shown in title block; Organization: Not shown in title block; Address1: Not shown in title block; Address2: Not shown in title block; Address3: Not shown in title block; Address4: Not shown in title block; DocumentNumber: 1; Revision: Use project parameter SCH_Rev; SheetNumber: 5; SheetTotal: 5; PageSetup: Record=PageOptions¦CenterHorizontal=True¦CenterVertical=True¦PrintScale=1.00¦XCorrection=1.00¦YCorrection=1.00¦PrintKind=0¦BorderSize=5000000¦LeftOffset=0¦BottomOffset=0¦Orientation=2¦PaperLength=1000¦PaperWidth=1000¦Scale=100¦PaperSource=15¦PrintQuality=600¦MediaType=1¦DitherType=10¦PaperKind=Letter¦PrintScaleMode=1
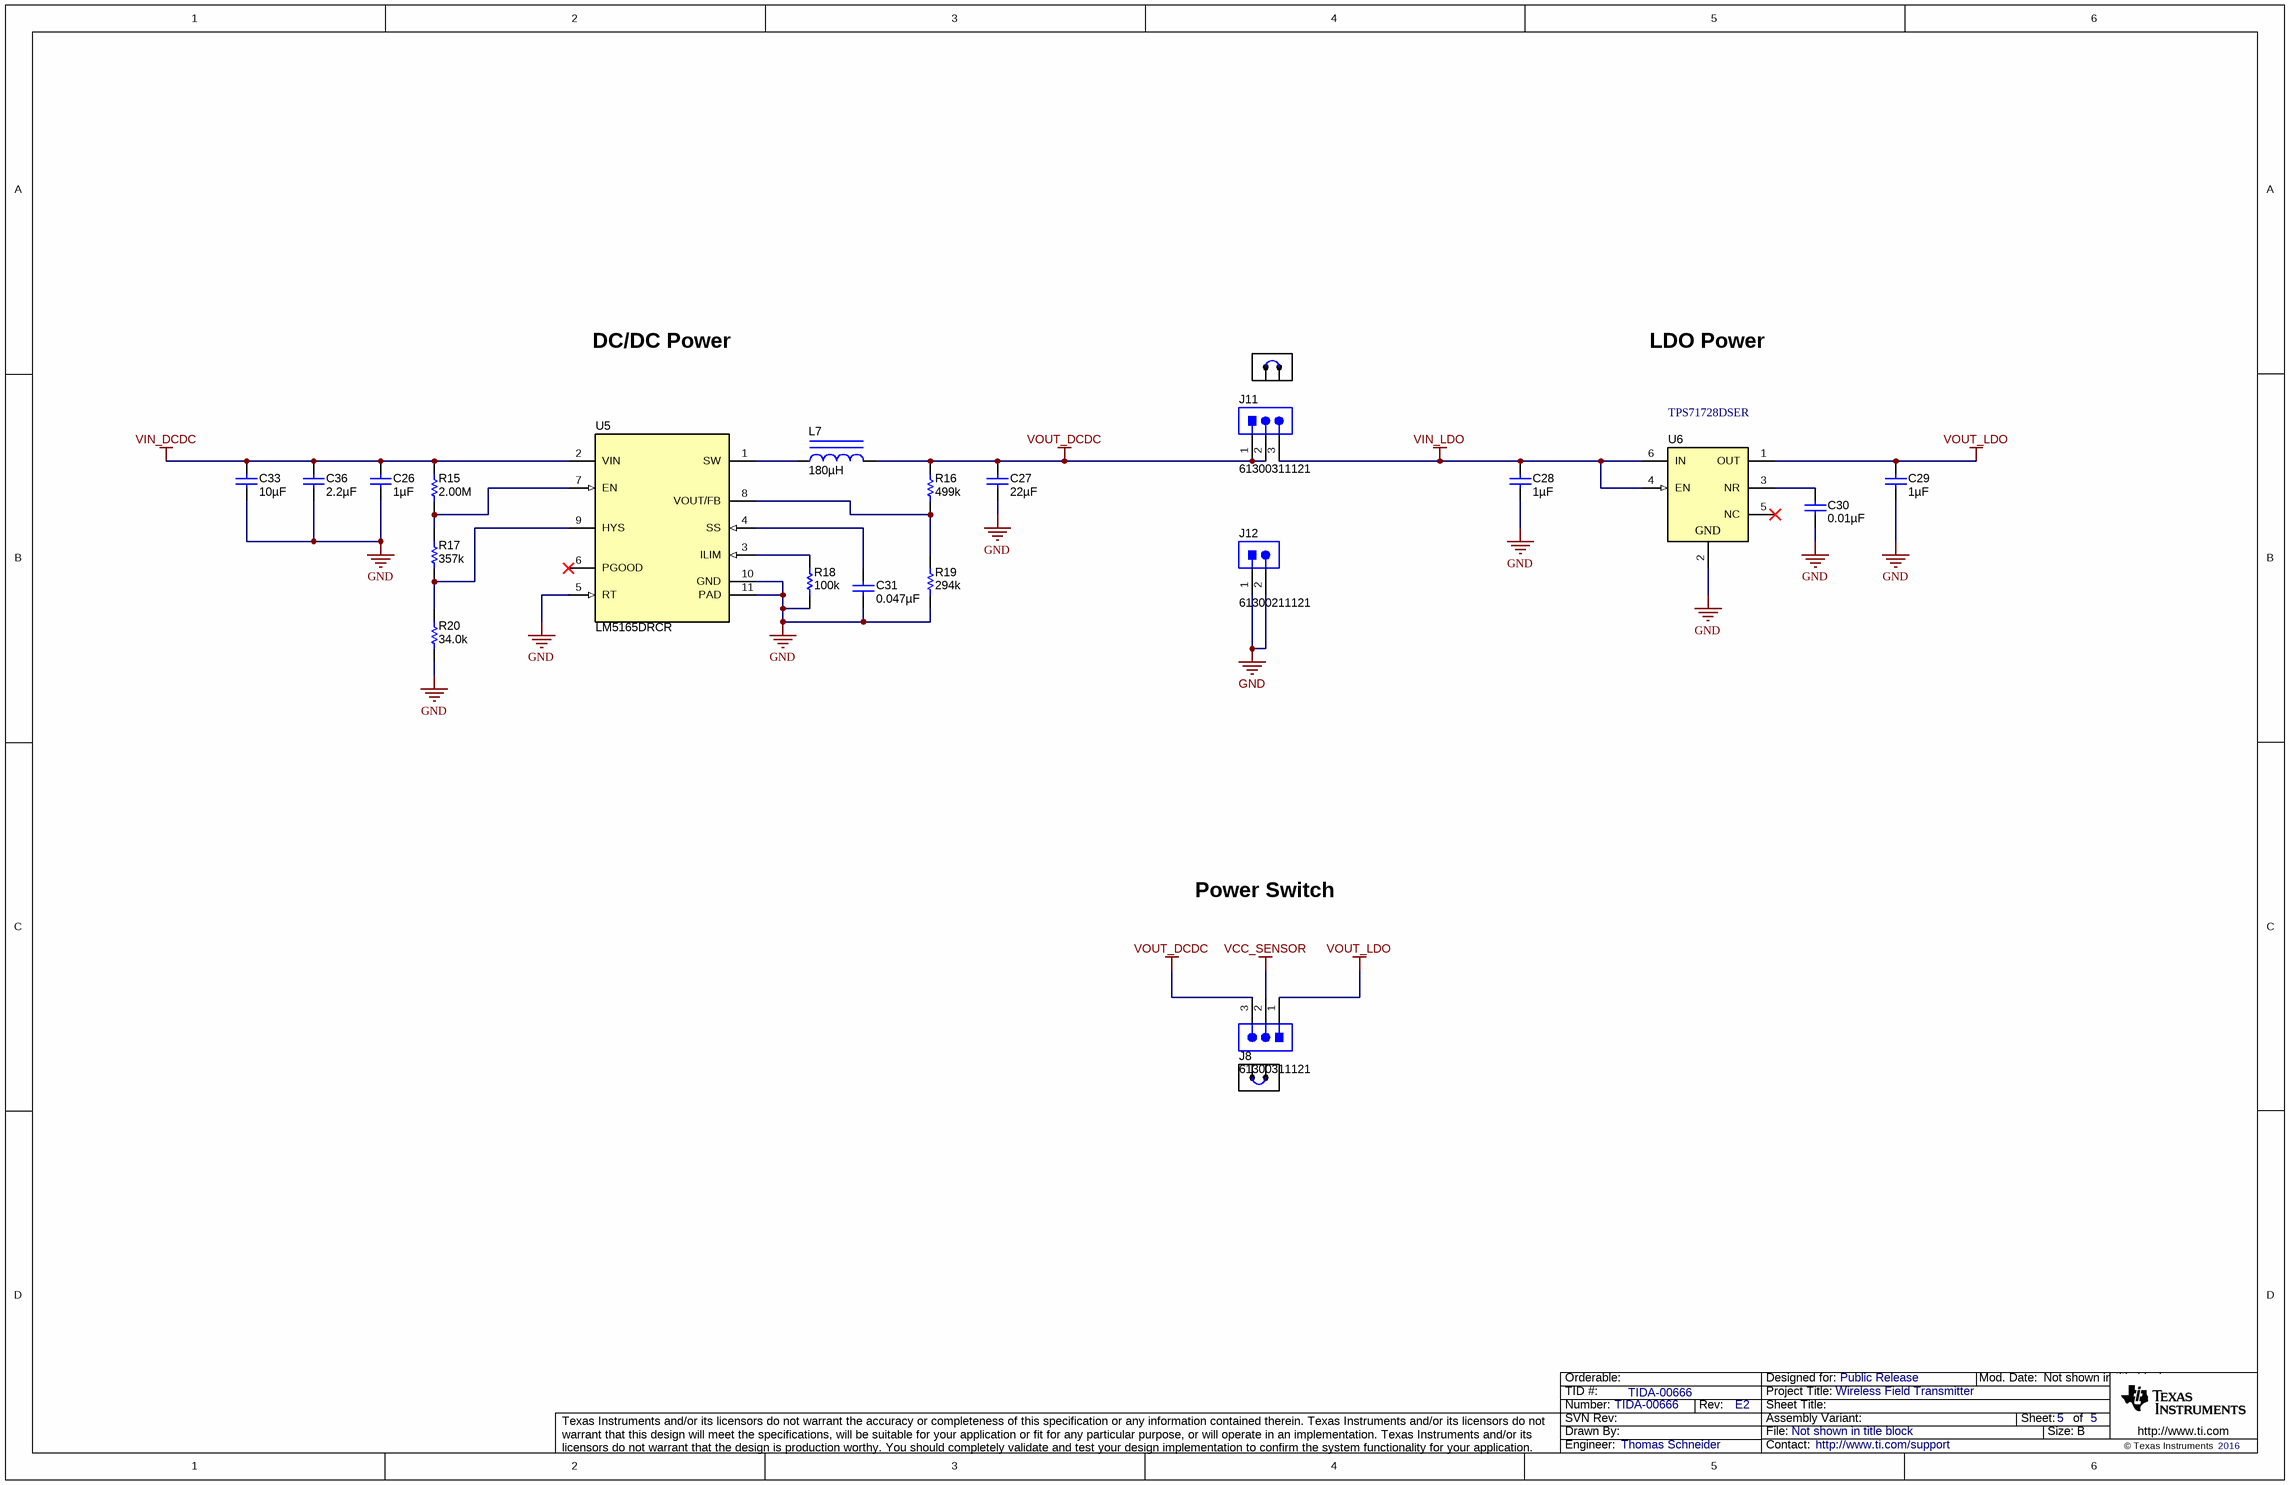
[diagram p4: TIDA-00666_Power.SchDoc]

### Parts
C26  ValueDisplayed: 1µF  [1206]  (hidden comment: GRM31CR72A105KA01L)
C27  ValueDisplayed: 22µF  [1206]  (hidden comment: GRM31CR71A226KE15L)
C28  ValueDisplayed: 1µF  [0402]  (hidden comment: C1005X7S1A105K050BC)
C29  ValueDisplayed: 1µF  [0402]  (hidden comment: C1005X7S1A105K050BC)
C30  ValueDisplayed: 0.01µF  [0402]  (hidden comment: C1005X7R1C103K050BA)
C31  ValueDisplayed: 0.047µF  [0402]  (hidden comment: GRM155R71C473KA01D)
C33  ValueDisplayed: 10µF  [1210_270]  (hidden comment: GRM32ER71J106KA12L)
C36  ValueDisplayed: 2.2µF  [1206]  (hidden comment: UMK316B7225KL-T)
J8  61300311121  [WURTH_61300311121]
J11  61300311121  [WURTH_61300311121]
J12  61300211121  [WURTH_61300211121]
L7  ValueDisplayed: 180µH  [LPS4018]  (hidden comment: LPS4018-184MLB)
R15  ValueDisplayed: 2.00M  [0402]  (hidden comment: CRCW04022M00FKED)
R16  ValueDisplayed: 499k  [0402]  (hidden comment: CRCW0402499KFKED)
R17  ValueDisplayed: 357k  [0402]  (hidden comment: CRCW0402357KFKED)
R18  ValueDisplayed: 100k  [0402]  (hidden comment: CRCW0402100KFKED)
R19  ValueDisplayed: 294k  [0402]  (hidden comment: CRCW0402294KFKED)
R20  ValueDisplayed: 34.0k  [0402]  (hidden comment: CRCW040234K0FKED)
SH-J3  969102-0000-DA  [SNT-100-BK-G]  (value not drawn)
SH-J4  969102-0000-DA  [SNT-100-BK-G]  (value not drawn)
U5  LM5165DRCR  [DRC0010J]
U6  TPS71728DSER  [DSE0006A]

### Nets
GND: C26.2 C27.2 C28.2 C29.2 C30.2 C31.2 C33.2 C36.2 J12.1 J12.2 R18.1 R19.1 R20.1 U5.5(RT) U5.10(GND) U5.11(PAD) U6.2(GND)
VCC_SENSOR: J8.2
VIN_DCDC: C26.1 C33.1 C36.1 R15.2 U5.2(VIN)
VIN_LDO: C28.1 J11.3 U6.4(EN) U6.6(IN)
VOUT_DCDC: C27.1 J8.3 J11.1 J11.2 L7.2 R16.2
VOUT_LDO: C29.1 J8.1 U6.1(OUT)
NetC30_1: C30.1 U6.3(NR)
NetC31_1: C31.1 U5.4(SS)
NetL7_1: L7.1 U5.1(SW)
NetR15_1: R15.1 R17.2 U5.7(EN)
NetR16_1: R16.1 R19.2 U5.8(VOUT/FB)
NetR17_1: R17.1 R20.2 U5.9(HYS)
NetR18_2: R18.2 U5.3(ILIM)

Not connected (* = marked no-connect by the designer): U5 6(PGOOD)*; U6 5(NC)*

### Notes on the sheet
- DC/DC Power
- LDO Power
- Power Switch

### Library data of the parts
C26 = GRM31CR72A105KA01L: as C21 on sheet TIDA-00666_DAC
C27 = GRM31CR71A226KE15L: CAP, CERM, 22 µF, 10 V, +/- 10%, X7R, 1206; Manufacturer: MuRata; Polarized: N; CompType: Capacitor; Value: 22uF; U/M: EA; Cap_F: 0.000022; Tolerance_%: 10; Value1: Unknown; Value2: 10V; TaMin_C: -55; TaMax_C: 125; AEC Category: Q200
C28 C29 = C1005X7S1A105K050BC: CAP, CERM, 1 µF, 10 V, +/- 10%, X7S, 0402; Manufacturer: TDK; Polarized: N; CompType: Capacitor; Value: 1uF; U/M: EA; Cap_F: 0.000001; Tolerance_%: 10; Value1: Unknown; Value2: 10V; TaMin_C: -55; TaMax_C: 125; AEC Category: Q200
C30 = C1005X7R1C103K050BA: CAP, CERM, 0.01 µF, 16 V, +/- 10%, X7R, 0402; Manufacturer: TDK; Polarized: N; CompType: Capacitor; Value: 0.01uF; U/M: EA; Cap_F: 0.00000001; Tolerance_%: 10; ESR_ohm: 0.0623; Value1: 0.0623 ohm; VDC_V: 16; Value2: 16V; TaMin_C: -55; TaMax_C: 125; AEC Category: Q200
C31 = GRM155R71C473KA01D: CAP, CERM, 0.047 µF, 16 V, +/- 10%, X7R, 0402; Manufacturer: MuRata; Polarized: N; CompType: Capacitor; Value: 0.047uF; U/M: EA; Cap_F: 0.000000047; Tolerance_%: 10; Value1: Unknown; VDC_V: 16; Value2: 16V; TaMin_C: -55; TaMax_C: 125; AEC Category: Q200
C33 = GRM32ER71J106KA12L: CAP, CERM, 10 µF, 63 V, +/- 10%, X7R, 1210; Manufacturer: MuRata; Polarized: N; CompType: Capacitor; Value: 10uF; U/M: EA; Cap_F: 0.00001; Tolerance_%: 10; Value1: Unknown; VDC_V: 63; Value2: 63V; TaMin_C: -55; TaMax_C: 125; Cap_Case: 1210; SizeArea_mm2: 8; SizeAreaWB_mm2: 14.7; SizeX_mm: 3.2; SizeY_mm: 2.5; SizeZ_mm: 2.7; AEC Category: Q200
C36 = UMK316B7225KL-T: CAP, CERM, 2.2 µF, 50 V, +/- 10%, X7R, 1206; Manufacturer: Taiyo Yuden; Polarized: N; CompType: Capacitor; Value: 2.2uF; U/M: EA; Cap_F: 0.0000022; Tolerance_%: 10; Value1: Unknown; VDC_V: 50; Value2: 50V; TaMin_C: -55; TaMax_C: 125; SizeArea_mm2: 5.12; SizeAreaWB_mm2: 10.92; SizeX_mm: 3.2; SizeY_mm: 1.6; SizeZ_mm: 1.35; AEC Category: Q200
J8 = 61300311121: Header, 2.54 mm, 3x1, Gold, TH; Manufacturer: Wurth Elektronik; SymbolCreator: a0799628; U/M: EA
J11 = 61300311121: as J6 on sheet TIDA-00666_DAC
J12 = 61300211121: as J7 on sheet TIDA-00666_MCU
L7 = LPS4018-184MLB: Inductor, Shielded Drum Core, Ferrite, 180 µH, 0.27 A, 2.5 ohm, SMD; Manufacturer: Coilcraft; Value: 180uH; Ind_H: 180.0E-6; Imax_A: 0.27; Irms: 0.36A @ 40C rise; Isat: 0.27A @ 30% inductance drop; DCR_ohm: 2.5; Value1: 2.5 ohm; Value2: 0.27A; AEC Category: Q200
R15 = CRCW04022M00FKED: RES, 2.00 M, 1%, 0.063 W, 0402; Manufacturer: Vishay-Dale; CompType: Resistor; Value: 2.00Meg; Res_ohm: 2000000; Value_Code: 2M00; Tolerance_%: 1; Power_W: 0.063; Value2: 0.063W; VDC_V: 50; TempCo: 100 ppm/C; EIA_Code: E96; U/M: EA; AEC Category: Q200
R16 = CRCW0402499KFKED: RES, 499 k, 1%, 0.063 W, 0402; Manufacturer: Vishay-Dale; CompType: Resistor; Value: 499k; Res_ohm: 499000; Tolerance_%: 1; Power_W: 0.063; Value2: 0.063W; VDC_V: 50; TempCo: 100 ppm/C; EIA_Code: E96; U/M: EA; AEC Category: Q200
R17 = CRCW0402357KFKED: RES, 357 k, 1%, 0.063 W, 0402; Manufacturer: Vishay-Dale; CompType: Resistor; Value: 357k; Res_ohm: 357000; Tolerance_%: 1; Power_W: 0.063; Value2: 0.063W; VDC_V: 50; TempCo: 100 ppm/C; EIA_Code: E96; U/M: EA; AEC Category: Q200
R18 = CRCW0402100KFKED: RES, 100 k, 1%, 0.063 W, 0402; Manufacturer: Vishay-Dale; CompType: Resistor; Value: 100k; Res_ohm: 100000; Tolerance_%: 1; Power_W: 0.063; Value2: 0.063W; VDC_V: 50; TempCo: 100 ppm/C; EIA_Code: E96; U/M: EA; AEC Category: Q200
R19 = CRCW0402294KFKED: RES, 294 k, 1%, 0.063 W, 0402; Manufacturer: Vishay-Dale; CompType: Resistor; Value: 294k; Res_ohm: 294000; Tolerance_%: 1; Power_W: 0.063; Value2: 0.063W; VDC_V: 50; TempCo: 100 ppm/C; EIA_Code: E96; U/M: EA; AEC Category: Q200
R20 = CRCW040234K0FKED: RES, 34.0 k, 1%, 0.063 W, 0402; Manufacturer: Vishay-Dale; CompType: Resistor; Value: 34.0k; Res_ohm: 34000; Value_Code: 34k0; Tolerance_%: 1; Power_W: 0.063; Value2: 0.063W; VDC_V: 50; TempCo: 100 ppm/C; EIA_Code: E96; U/M: EA; AEC Category: Q200
SH-J3 SH-J4 = 969102-0000-DA: as SH-J5 on sheet TIDA-00666_MCU
U5 = LM5165DRCR: 3.0-V to 65-V Input, 150-mA Output, Ultra-Low Quiescent (ULQ) Synchronous Step-Down Voltage Regulator, DRC0010J; Alternate PartNumber: LM5165DRCT; Manufacturer: Texas Instruments; SymbolCreator: Altium; CompType: IC; U/M: EA
U6 = TPS71728DSER: Single Output High PSRR LDO, 150 mA, Fixed 2.8 V Output, 2.5 to 6.5 V Input, with Low IQ, 6-pin WSON (DSE), -40 to 85 degC, Green (RoHS & no Sb/Br); Manufacturer: Texas Instruments; Alternate PartNumber: Equivalent; Accuracy(%): 3; Fixed Output Options(V): 2.8; Iout(Max)(A): 0.15; Iq(Typ)(mA): 0.05; SubFamily: Single Channel LDO; Vdo(Typ)(mV): 170; Vin(Max)(V): 6.5; Vin(Min)(V): 2.5

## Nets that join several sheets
GND: TIDA-00666_MCU (35 pins), TIDA-00666_DAC (13 pins), TIDA-00666_Power (17 pins)
VCC_SENSOR: TIDA-00666_MCU (6 pins), TIDA-00666_DAC (J6.1 J10.1 R14.1), TIDA-00666_Power (J8.2)
VIN_DCDC: TIDA-00666_DAC (J3.1), TIDA-00666_Power (5 pins)
CLK: TIDA-00666_MCU (U3.26), TIDA-00666_DAC (U4.4)
CS: TIDA-00666_MCU (U3.24), TIDA-00666_DAC (U4.6)
nDAC_ERROR: TIDA-00666_MCU (U3.15), TIDA-00666_DAC (R14.2 U4.7)
SIMO: TIDA-00666_MCU (U3.25), TIDA-00666_DAC (U4.5)
SOMI: TIDA-00666_MCU (U3.23), TIDA-00666_DAC (U4.8)

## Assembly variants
001: not fitted C1 C10 C13 C14 C33 C34 C35 FID1 FID2 FID3 J12 R8 R17 R20 R22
